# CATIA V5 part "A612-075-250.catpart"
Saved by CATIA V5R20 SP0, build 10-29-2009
Part number: A612-075-250
Source: Unknown
Property "A": "25.000"
Property "ARTICLENO": "A612-075-250"
Property "B": "35.000"
Property "BOMINFO": "A612-075-250"
Property "CODE": "A612-075-250"
Property "D": "17.500"
Property "FORM": "B"
Property "L": "250.000"
Property "L1": "45.000"
Property "L2": "80.000"
Property "L3": "0.000"
Property "LINA": "A612-075-250"
Property "NB": "A612-075-250"
Property "NBSYN": "$CODE."
Property "NN": "A612"
Property "NT": "CDI 3357 E-Type Wear Plates, steel and self-lubricating"
Property "SUPPLIER": "CF"
Property "T": "25.000"
Property "W": "75.000"
Bounding box of the stored display mesh (mm): x 0 to 25, y 0 to 250, z 0 to 75
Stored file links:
  C:\Users\Utente\Desktop\3D files A612\A612-075-250.catpart
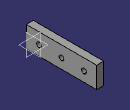
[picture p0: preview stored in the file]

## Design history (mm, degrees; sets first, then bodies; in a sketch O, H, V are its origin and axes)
Body1 "Geometry.1" (main body)
  Solid1 "A612-075-250.catpart": solid without history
